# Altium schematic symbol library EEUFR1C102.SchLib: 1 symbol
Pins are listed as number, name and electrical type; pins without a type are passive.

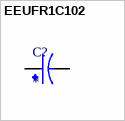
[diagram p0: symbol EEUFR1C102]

## EEUFR1C102
designator C?
Tutup Aluminium Lytic 1000uF 16V 20% (10 X 16mm) Radial 5mm 1790mA 8000h 105C Massal; MF: Panasonic Electronic; MP: EEU-FR1C102
footprint CAPPRD500W60D1000H1600
pins: N, P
